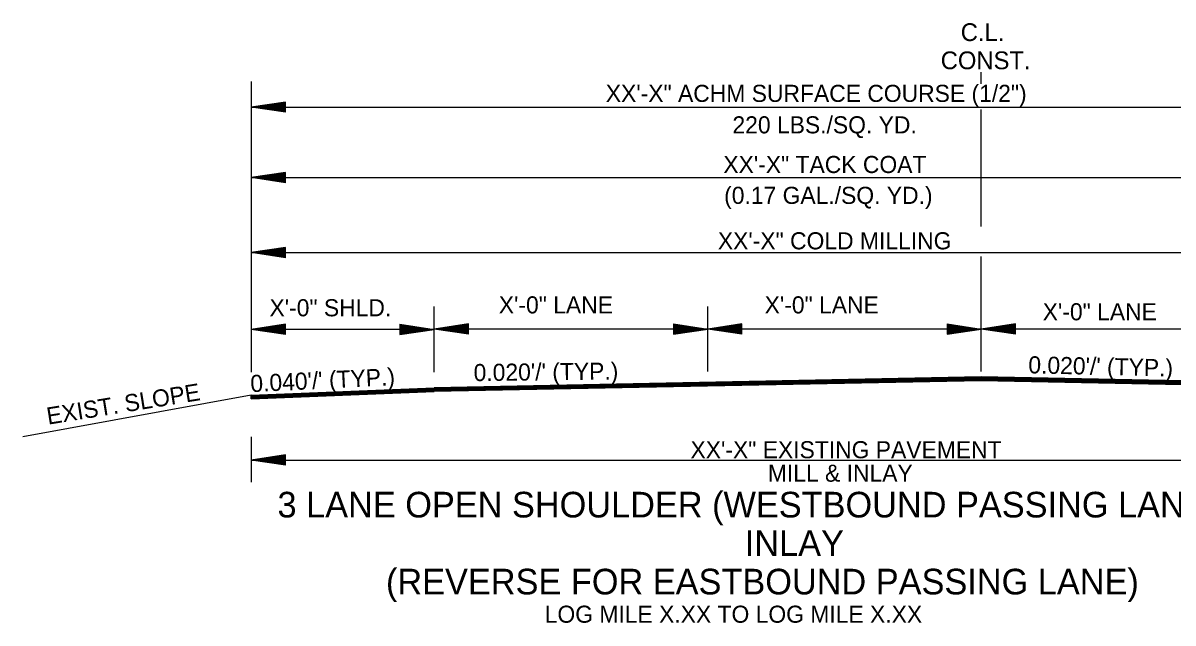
# Model space of a CAD drawing. Extents: x 542112 to 1930787, y -1968972 to 596640.
# Drawn here: x 546591 to 547096, y -1961191 to -1960928 of the extents above; entities that cross this region are included whole.
import ezdxf

# ---------------------------------------------------------------- set-up
doc = ezdxf.new("R2010")
doc.units = 0
doc.layers.add('R_Draft', color=7, linetype='Continuous')

msp = doc.modelspace()

# ---------------------------------------------------------------- linework, layer by layer
at = {"layer": 'R_Draft'}
for p, q in [((546691.52, -1960953.41), (546691.52, -1961080.84)), ((547011.71, -1960954.41), (547011.71, -1960949.28)), ((546706.52, -1960962.42), (546691.52, -1960964.67)), ((546706.52, -1960962.8), (546694.03, -1960964.67)), ((546706.52, -1960963.18), (546696.61, -1960964.67)), ((546706.52, -1960963.55), (546699.11, -1960964.67)), ((546706.52, -1960963.94), (546701.65, -1960964.67)), ((546706.52, -1960964.32), (546704.15, -1960964.67)), ((546706.52, -1960966.92), (546706.52, -1960962.42)), ((546691.52, -1960964.67), (547211.97, -1960964.67)), ((546706.52, -1960966.92), (546691.52, -1960964.67)), ((546706.52, -1960966.55), (546694.03, -1960964.67)), ((546706.52, -1960966.16), (546696.61, -1960964.67)), ((546706.52, -1960965.79), (546699.11, -1960964.67)), ((546706.52, -1960965.4), (546701.65, -1960964.67)), ((546706.52, -1960965.02), (546704.15, -1960964.67)), ((547011.71, -1961017.01), (547011.71, -1960965.65)), ((546706.52, -1960993.29), (546691.52, -1960995.54)), ((546706.52, -1960993.67), (546694.03, -1960995.54)), ((546706.52, -1960994.05), (546696.61, -1960995.54)), ((546706.52, -1960994.42), (546699.11, -1960995.54)), ((546706.52, -1960997.79), (546706.52, -1960993.29)), ((546691.52, -1960995.54), (547211.97, -1960995.54)), ((546706.52, -1960997.79), (546691.52, -1960995.54)), ((546706.52, -1960997.42), (546694.03, -1960995.54)), ((546706.52, -1960997.03), (546696.61, -1960995.54)), ((546706.52, -1960996.66), (546699.11, -1960995.54)), ((546706.52, -1960994.81), (546701.65, -1960995.54)), ((546706.52, -1960996.27), (546701.65, -1960995.54)), ((546706.52, -1960995.19), (546704.15, -1960995.54)), ((546706.52, -1960995.89), (546704.15, -1960995.54)), ((546706.52, -1961026.22), (546691.52, -1961028.47)), ((546691.52, -1961028.47), (547211.97, -1961028.47)), ((546706.52, -1961030.72), (546691.52, -1961028.47)), ((546706.52, -1961026.6), (546694.03, -1961028.47)), ((546706.52, -1961030.35), (546694.03, -1961028.47)), ((546706.52, -1961026.98), (546696.61, -1961028.47)), ((546706.52, -1961029.96), (546696.61, -1961028.47)), ((546706.52, -1961027.35), (546699.11, -1961028.47)), ((546706.52, -1961029.59), (546699.11, -1961028.47)), ((546706.52, -1961027.74), (546701.65, -1961028.47)), ((546706.52, -1961029.2), (546701.65, -1961028.47)), ((546706.52, -1961028.12), (546704.15, -1961028.47)), ((546706.52, -1961028.82), (546704.15, -1961028.47)), ((546706.52, -1961030.72), (546706.52, -1961026.22)), ((547011.71, -1961080.67), (547011.71, -1961030.23)), ((546771.78, -1961080.67), (546771.78, -1961052.11)), ((546771.78, -1961080.84), (546771.78, -1961052.11)), ((546891.78, -1961080.67), (546891.78, -1961052.11)), ((546706.52, -1961059.93), (546691.52, -1961062.18)), ((546706.52, -1961064.43), (546706.52, -1961059.93)), ((546756.78, -1961059.93), (546771.78, -1961062.18)), ((546756.78, -1961059.93), (546756.78, -1961064.43)), ((546786.78, -1961059.76), (546771.78, -1961062.01)), ((546786.78, -1961060.13), (546774.29, -1961062.01)), ((546786.78, -1961064.26), (546786.78, -1961059.76)), ((546876.78, -1961059.76), (546891.78, -1961062.01)), ((546876.78, -1961059.76), (546876.78, -1961064.26)), ((546876.78, -1961060.13), (546889.28, -1961062.01)), ((546906.78, -1961059.76), (546891.78, -1961062.01)), ((546906.78, -1961060.13), (546894.29, -1961062.01)), ((546906.78, -1961064.26), (546906.78, -1961059.76)), ((546996.71, -1961059.76), (547011.71, -1961062.01)), ((546996.71, -1961059.76), (546996.71, -1961064.26)), ((546996.71, -1961060.13), (547009.21, -1961062.01)), ((547026.71, -1961059.76), (547011.71, -1961062.01)), ((547026.71, -1961060.13), (547014.22, -1961062.01)), ((547026.71, -1961064.26), (547026.71, -1961059.76)), ((546771.78, -1961062.18), (546691.52, -1961062.18)), ((546706.52, -1961064.43), (546691.52, -1961062.18)), ((546706.52, -1961060.3), (546694.03, -1961062.18)), ((546706.52, -1961064.05), (546694.03, -1961062.18)), ((546706.52, -1961060.68), (546696.61, -1961062.18)), ((546706.52, -1961063.67), (546696.61, -1961062.18)), ((546706.52, -1961061.06), (546699.11, -1961062.18)), ((546706.52, -1961063.29), (546699.11, -1961062.18)), ((546706.52, -1961061.44), (546701.65, -1961062.18)), ((546706.52, -1961062.9), (546701.65, -1961062.18)), ((546706.52, -1961061.82), (546704.15, -1961062.18)), ((546706.52, -1961062.53), (546704.15, -1961062.18)), ((546756.78, -1961060.3), (546769.28, -1961062.18)), ((546756.78, -1961060.68), (546766.7, -1961062.18)), ((546756.78, -1961061.06), (546764.2, -1961062.18)), ((546756.78, -1961061.45), (546761.66, -1961062.18)), ((546756.78, -1961061.82), (546759.15, -1961062.18)), ((546756.78, -1961064.43), (546771.78, -1961062.18)), ((546756.78, -1961062.91), (546761.66, -1961062.18)), ((546756.78, -1961063.67), (546766.7, -1961062.18)), ((546756.78, -1961064.05), (546769.28, -1961062.18)), ((546756.78, -1961063.29), (546764.2, -1961062.18)), ((546756.78, -1961062.53), (546759.15, -1961062.18)), ((546891.78, -1961062.01), (546771.78, -1961062.01)), ((546786.78, -1961064.26), (546771.78, -1961062.01)), ((546786.78, -1961063.88), (546774.29, -1961062.01)), ((546786.78, -1961060.51), (546776.87, -1961062.01)), ((546786.78, -1961063.5), (546776.87, -1961062.01)), ((546786.78, -1961060.89), (546779.37, -1961062.01)), ((546786.78, -1961063.12), (546779.37, -1961062.01)), ((546786.78, -1961061.27), (546781.91, -1961062.01)), ((546786.78, -1961062.73), (546781.91, -1961062.01)), ((546786.78, -1961061.65), (546784.41, -1961062.01)), ((546786.78, -1961062.36), (546784.41, -1961062.01)), ((546876.78, -1961060.51), (546886.7, -1961062.01)), ((546876.78, -1961060.89), (546884.2, -1961062.01)), ((546876.78, -1961061.28), (546881.66, -1961062.01)), ((546876.78, -1961061.65), (546879.15, -1961062.01)), ((546876.78, -1961064.26), (546891.78, -1961062.01)), ((546876.78, -1961062.74), (546881.66, -1961062.01)), ((546876.78, -1961063.5), (546886.7, -1961062.01)), ((546876.78, -1961063.88), (546889.28, -1961062.01)), ((546876.78, -1961063.12), (546884.2, -1961062.01)), ((546876.78, -1961062.36), (546879.15, -1961062.01)), ((547011.71, -1961062.01), (546891.78, -1961062.01)), ((546906.78, -1961064.26), (546891.78, -1961062.01)), ((546906.78, -1961063.88), (546894.29, -1961062.01)), ((546906.78, -1961060.51), (546896.87, -1961062.01)), ((546906.78, -1961063.5), (546896.87, -1961062.01)), ((546906.78, -1961060.89), (546899.37, -1961062.01)), ((546906.78, -1961063.12), (546899.37, -1961062.01)), ((546906.78, -1961061.27), (546901.91, -1961062.01)), ((546906.78, -1961062.73), (546901.91, -1961062.01)), ((546906.78, -1961061.65), (546904.41, -1961062.01)), ((546906.78, -1961062.36), (546904.41, -1961062.01)), ((546996.71, -1961060.51), (547006.63, -1961062.01)), ((546996.71, -1961060.89), (547004.13, -1961062.01)), ((546996.71, -1961061.28), (547001.59, -1961062.01)), ((546996.71, -1961061.65), (546999.08, -1961062.01)), ((546996.71, -1961064.26), (547011.71, -1961062.01)), ((546996.71, -1961062.74), (547001.59, -1961062.01)), ((546996.71, -1961063.5), (547006.63, -1961062.01)), ((546996.71, -1961063.88), (547009.21, -1961062.01)), ((546996.71, -1961063.12), (547004.13, -1961062.01)), ((546996.71, -1961062.36), (546999.08, -1961062.01)), ((547131.97, -1961062.01), (547011.71, -1961062.01)), ((547026.71, -1961064.26), (547011.71, -1961062.01)), ((547026.71, -1961063.88), (547014.22, -1961062.01)), ((547026.71, -1961060.51), (547016.8, -1961062.01)), ((547026.71, -1961063.5), (547016.8, -1961062.01)), ((547026.71, -1961060.89), (547019.29, -1961062.01)), ((547026.71, -1961063.12), (547019.29, -1961062.01)), ((547026.71, -1961061.27), (547021.84, -1961062.01)), ((547026.71, -1961062.73), (547021.84, -1961062.01)), ((547026.71, -1961061.65), (547024.34, -1961062.01)), ((547026.71, -1961062.36), (547024.34, -1961062.01)), ((547011.71, -1961082.95), (546771.78, -1961087.75)), ((547011.71, -1961083.25), (546771.79, -1961088.05)), ((547011.71, -1961083.55), (546771.8, -1961088.35)), ((547011.71, -1961083.85), (546771.8, -1961088.65)), ((547011.71, -1961084.15), (546771.81, -1961088.95)), ((547011.71, -1961084.45), (546771.81, -1961089.25)), ((547011.71, -1961084.65), (546771.82, -1961089.45)), ((547131.97, -1961085.35), (547011.71, -1961082.95)), ((547131.97, -1961085.65), (547011.71, -1961083.25)), ((547131.96, -1961085.95), (547011.71, -1961083.55)), ((547131.95, -1961086.25), (547011.71, -1961083.85)), ((547131.95, -1961086.55), (547011.71, -1961084.15)), ((547131.94, -1961086.85), (547011.71, -1961084.45)), ((547131.94, -1961087.05), (547011.71, -1961084.65)), ((546691.52, -1961090.96), (546771.78, -1961087.75)), ((546691.52, -1961091.26), (546771.8, -1961088.05)), ((546691.52, -1961091.56), (546771.81, -1961088.35)), ((546691.52, -1961091.86), (546771.82, -1961088.65)), ((546691.52, -1961092.16), (546771.83, -1961088.94)), ((546691.52, -1961092.46), (546771.84, -1961089.24)), ((546691.52, -1961092.66), (546771.85, -1961089.44)), ((546691.52, -1961090.96), (546591.45, -1961109.33)), ((546691.52, -1961092.66), (546691.52, -1961090.96)), ((546691.52, -1961090.96), (546691.52, -1961092.66)), ((546691.52, -1961109.22), (546691.52, -1961129.22)), ((546706.52, -1961117.22), (546691.52, -1961119.47)), ((546691.52, -1961119.47), (547211.97, -1961119.47)), ((546706.52, -1961121.72), (546691.52, -1961119.47)), ((546706.52, -1961117.6), (546694.03, -1961119.47)), ((546706.52, -1961121.35), (546694.03, -1961119.47)), ((546706.52, -1961117.98), (546696.61, -1961119.47)), ((546706.52, -1961120.96), (546696.61, -1961119.47)), ((546706.52, -1961118.35), (546699.11, -1961119.47)), ((546706.52, -1961120.59), (546699.11, -1961119.47)), ((546706.52, -1961118.74), (546701.65, -1961119.47)), ((546706.52, -1961120.2), (546701.65, -1961119.47)), ((546706.52, -1961119.12), (546704.15, -1961119.47)), ((546706.52, -1961119.82), (546704.15, -1961119.47)), ((546706.52, -1961121.72), (546706.52, -1961117.22))]:
    msp.add_line(p, q, dxfattribs=at)

# ---------------------------------------------------------------- texts
for s, height, p in [('C.L.', 7.8, (547002.73, -1960935.67)), ('CONST.', 7.8, (546993.95, -1960948.03)), ('XX\'-X" ACHM SURFACE COURSE (1/2")', 7.5, (546847.06, -1960962.37)), ('220 LBS./SQ. YD. ', 7.5, (546902.61, -1960976.17)), ('XX\'-X" TACK COAT', 7.5, (546898.61, -1960993.56)), ('(0.17 GAL./SQ. YD.)', 7.5, (546898.96, -1961007.1)), ('XX\'-X" COLD MILLING', 7.5, (546896.2, -1961027.04)), ('X\'-0" SHLD.', 7.5, (546699.56, -1961056.41)), ('X\'-0" LANE', 7.5, (546800.13, -1961055.14)), ('X\'-0" LANE', 7.5, (546916.72, -1961055.14)), ('X\'-0" LANE', 7.5, (547038.67, -1961058.17)), ('XX\'-X" EXISTING PAVEMENT', 7.5, (546884.2, -1961118.68)), ('MILL & INLAY', 7.5, (546918.13, -1961128.96)), ('3 LANE OPEN SHOULDER (WESTBOUND PASSING LANE)', 11.25, (546703.07, -1961144.65)), (' INLAY', 11.25, (546903.84, -1961161.53)), ('(REVERSE FOR EASTBOUND PASSING LANE)', 11.25, (546750.64, -1961178.4)), ('LOG MILE X.XX TO LOG MILE X.XX', 7.5, (546820.27, -1961190.83))]:
    msp.add_text(s, height=height, dxfattribs=at).set_placement(p)
for s, rotation, p in [("0.020'/' (TYP.)", 358.7013, (547032.31, -1961081.39)), ("0.040'/' (TYP.)", 2.8401, (546691.36, -1961089.71)), ("0.020'/' (TYP.)", 0.6486, (546789.12, -1961084.85)), ('EXIST. SLOPE', 9.1534, (546602.46, -1961103.96))]:
    msp.add_text(s, height=7.5, rotation=rotation, dxfattribs=at).set_placement(p)

doc.saveas('drawing.dxf')
